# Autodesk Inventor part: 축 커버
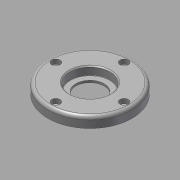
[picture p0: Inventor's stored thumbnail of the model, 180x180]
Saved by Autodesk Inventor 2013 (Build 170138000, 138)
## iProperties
Created: 2015-10
Part Number: 축 커버
Document SubType Name: Modeling
Designer: mdu
Density: 7.86 g/cm^3
Material: 강철, 연강
Mass: 322.464 g
Surface Area: 133.703 cm^2
Volume: 41.026 cm^3
Author: mdu
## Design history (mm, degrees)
sketch "스케치1"
  geometry: C1 r 40 at (0, 0) reference; C2 r 26 at (0, 0) reference; 1 further point
  node "참조1"
  node "참조2"
extrude "돌출1" new body sketch "스케치1" distance "d0" = 10; taper "d1" = 0 deg
extrude "돌출2" join sketch "스케치1" distance "d2" = 3; taper "d3" = 0 deg
hole "구멍1" diameter "d6" = 27; stored, may be unused: countersink angle "d10" = 90 deg, drill point angle "d12" = 118 deg; dims "d4" = 10, "d5" = 10, "d7" = 6, "d8" = 38, "d9" = 8, "d11" = 8
sketch "스케치2"
  geometry: C1 r 20 at (0, 0); 1 further point
  constraints: 1 centre point, 1 coincident
  dimensions: "d13" = 40 diameter of C1
extrude "돌출3" cut sketch "스케치2" distance "d14" = 3; taper "d15" = 0 deg
sketch "스케치3"
  geometry: C1 r 1.621 at (0, 32.5) reference; 1 further point
hole "구멍2" sketch "스케치3" at (0, 32.5) diameter "d16" = 4.5; stored, may be unused: countersink angle "d20" = 90 deg, drill point angle "d22" = 118 deg; dims "d17" = 6, "d18" = 8, "d19" = 4.4, "d21" = 8
fillet "모깎기1" dims "d26" = 3, "d27" = 0.3
chamfer "모따기1" distance "d28" = 1; stored, may be unused: second distance "d29" = 2, angle "d30" = 45 deg
node "솔리드1"
pattern_circular "원형 패턴1" dims angle "d24" = 360 deg
node "참조3"
